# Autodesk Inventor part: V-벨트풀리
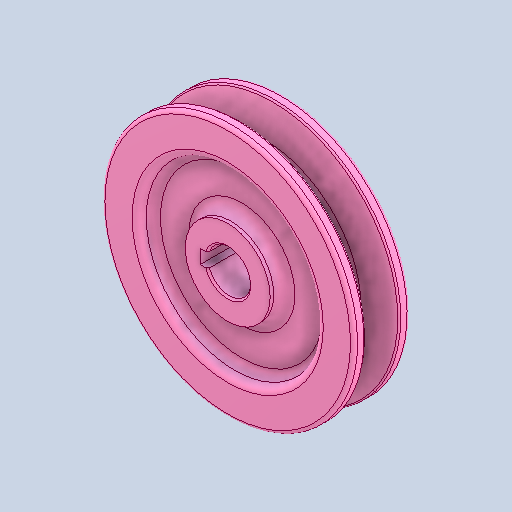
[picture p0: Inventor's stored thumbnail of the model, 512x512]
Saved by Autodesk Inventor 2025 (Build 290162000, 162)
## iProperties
Created: 2024-08
Part Number: V-벨트풀리
Material: 강철, 연강
Document SubType Name: Modeling
Designer: Administrator
Density: 7.86 g/cm^3
Appearance: 기본값
Author: jhkim
Sending System: Autodesk Inventor 2025
Preprocessor: ST-DEVELOPER v20
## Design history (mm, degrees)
feature "Solid1"
node "솔리드1"
